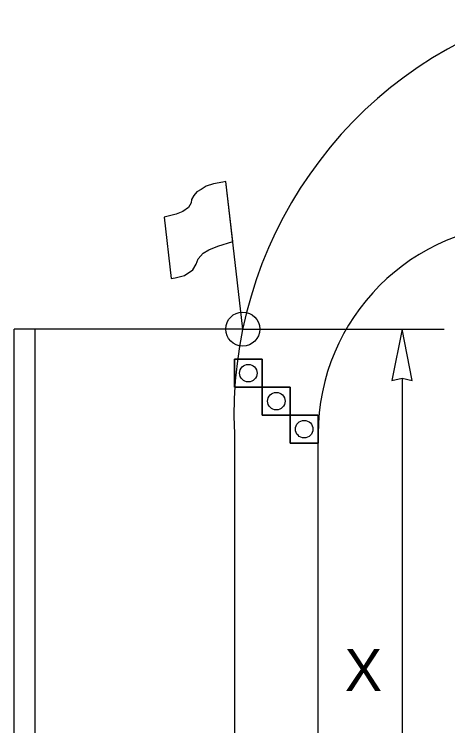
# Model space of a CAD drawing. Extents: x 99999.1 to 100095.7, y 99995 to 100010.7.
# Drawn here: x 100062.105 to 100062.932, y 100002.969 to 100004.325 of the extents above; entities that cross this region are included whole.
import ezdxf

# ---------------------------------------------------------------- set-up
doc = ezdxf.new("R2010")
doc.units = 0
for name, color, linetype in [('RD_ED_ShoulderPavedEdge', 7, 'Continuous'), ('RD_MK_LineDblYellowCenter', 7, 'Continuous'), ('RD_MK_LineEdgeWhite', 7, 'Continuous'), ('RD_MK_LineStop', 7, 'Continuous'), ('TR_WZ_FlaggingStation', 7, 'Continuous'), ('TR_WZ_TrafficCone', 7, 'Continuous'), ('TR_WZ_WorkZoneDetails', 7, 'Continuous'), ('TR_WZ_WorkZoneTextCurrent', 7, 'Continuous')]:
    doc.layers.add(name, color=color, linetype=linetype)

msp = doc.modelspace()

# ---------------------------------------------------------------- linework, layer by layer
at = {"layer": 'RD_ED_ShoulderPavedEdge'}
msp.add_lwpolyline([(100062.685, 100002.1759), (100062.685, 100003.5249)], dxfattribs=at)
msp.add_arc((100063.085, 100003.5249), 0.4, 90, 180, dxfattribs=at)
at = {"layer": 'RD_MK_LineDblYellowCenter'}
for p, q in [((100062.105, 100002.1759), (100062.105, 100003.7249)), ((100062.145, 100002.1759), (100062.145, 100003.7249))]:
    msp.add_line(p, q, dxfattribs=at)
at = {"layer": 'RD_MK_LineEdgeWhite'}
msp.add_line((100062.525, 100003.5249), (100062.525, 100002.1759), dxfattribs=at)
msp.add_arc((100063.3242, 100003.5615), 0.8, 107.3948, 182.6212, dxfattribs=at)
at = {"layer": 'RD_MK_LineStop'}
msp.add_line((100062.541, 100003.7249), (100062.105, 100003.7249), dxfattribs=at)
at = {"layer": 'TR_WZ_FlaggingStation'}
for p, q in [((100062.522, 100003.8918), (100062.5089, 100004.0062)), ((100062.541, 100003.7249), (100062.509, 100004.0059)), ((100062.391, 100003.9384), (100062.4043, 100003.8212)), ((100062.522, 100003.8918), (100062.522, 100003.8918))]:
    msp.add_line(p, q, dxfattribs=at)
for points in [[(100062.5089, 100004.0062), (100062.5032, 100004.0049), (100062.4854, 100004.0015), (100062.4715, 100003.9973), (100062.4619, 100003.9912), (100062.4533, 100003.9865), (100062.4477, 100003.9797), (100062.4434, 100003.9718), (100062.4429, 100003.9656), (100062.4375, 100003.9564), (100062.4267, 100003.949), (100062.4143, 100003.9438), (100062.391, 100003.9384)], [(100062.4043, 100003.8212), (100062.4124, 100003.8226), (100062.4301, 100003.8272), (100062.4458, 100003.8377), (100062.4523, 100003.8483), (100062.4562, 100003.8586), (100062.4653, 100003.8695), (100062.4763, 100003.8757), (100062.4936, 100003.8828), (100062.522, 100003.8918)]]:
    msp.add_lwpolyline(points, dxfattribs=at)
msp.add_circle((100062.541, 100003.7249), 0.0325, dxfattribs=at)
at = {"layer": 'TR_WZ_TrafficCone'}
for points in [[(100062.525, 100003.6142), (100062.525, 100003.6676), (100062.5783, 100003.6676), (100062.5783, 100003.6142), (100062.525, 100003.6142)], [(100062.5783, 100003.6142), (100062.5783, 100003.6676), (100062.525, 100003.6676), (100062.525, 100003.6142), (100062.5783, 100003.6142)], [(100062.5783, 100003.5609), (100062.5783, 100003.6142), (100062.6317, 100003.6142), (100062.6317, 100003.5609), (100062.5783, 100003.5609)], [(100062.6317, 100003.5609), (100062.6317, 100003.6142), (100062.5783, 100003.6142), (100062.5783, 100003.5609), (100062.6317, 100003.5609)], [(100062.6317, 100003.5076), (100062.6317, 100003.5609), (100062.685, 100003.5609), (100062.685, 100003.5076), (100062.6317, 100003.5076)], [(100062.685, 100003.5076), (100062.685, 100003.5609), (100062.6317, 100003.5609), (100062.6317, 100003.5076), (100062.685, 100003.5076)]]:
    msp.add_lwpolyline(points, dxfattribs=at)
for centre in [(100062.5517, 100003.6409), (100062.605, 100003.5876), (100062.6583, 100003.5342)]:
    msp.add_circle(centre, 0.0167, dxfattribs=at)
at = {"layer": 'TR_WZ_WorkZoneDetails'}
for p, q in [((100062.541, 100003.7249), (100062.925, 100003.7249)), ((100062.845, 100003.6312), (100062.845, 100002.5187))]:
    msp.add_line(p, q, dxfattribs=at)
msp.add_lwpolyline([(100062.845, 100003.7249), (100062.8257, 100003.6266), (100062.845, 100003.6312), (100062.8643, 100003.6266)], close=True, dxfattribs=at)

# ---------------------------------------------------------------- texts
at = {"layer": 'TR_WZ_WorkZoneTextCurrent'}
msp.add_text('X', height=0.08, dxfattribs=at).set_placement((100062.7356, 100003.0349))

doc.saveas('drawing.dxf')
